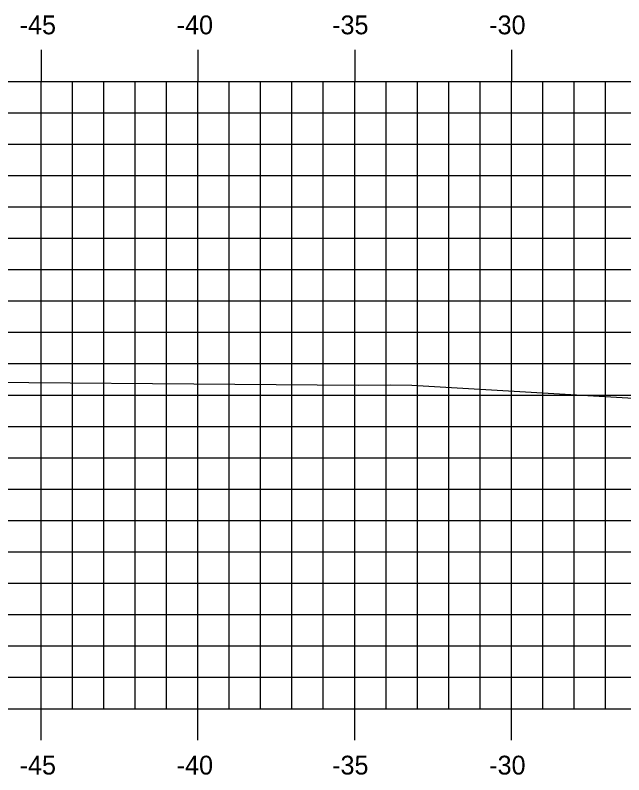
# Model space of a CAD drawing. Extents: x 1147855 to 1148025, y 608981 to 609091.
# Drawn here: x 1147892.39 to 1147911.79, y 609018.23 to 609042.44 of the extents above; entities that cross this region are included whole.
import ezdxf

# ---------------------------------------------------------------- set-up
doc = ezdxf.new("R2010")
doc.units = 0
for name, color, linetype in [('H_V ANNOTATION', 7, 'Continuous'), ('MAJOR', 7, 'Continuous'), ('MINOR', 7, 'Continuous'), ('S_Roadway_Centerline', 7, 'Continuous')]:
    doc.layers.add(name, color=color, linetype=linetype)

msp = doc.modelspace()

# ---------------------------------------------------------------- linework, layer by layer
at = {"layer": 'MAJOR'}
for p, q in [((1147893.211, 609041.337), (1147893.211, 609040.335)), ((1147898.211, 609041.337), (1147898.211, 609040.335)), ((1147903.211, 609041.337), (1147903.211, 609040.335)), ((1147908.211, 609041.337), (1147908.211, 609040.335)), ((1147868.211, 609040.335), (1148008.211, 609040.335)), ((1147868.211, 609040.335), (1148008.211, 609040.335)), ((1147893.211, 609020.335), (1147893.211, 609040.335)), ((1147898.211, 609020.335), (1147898.211, 609040.335)), ((1147903.211, 609020.335), (1147903.211, 609040.335)), ((1147908.211, 609020.335), (1147908.211, 609040.335)), ((1147868.211, 609035.335), (1148008.211, 609035.335)), ((1147868.211, 609030.335), (1148008.211, 609030.335)), ((1147868.211, 609025.335), (1148008.211, 609025.335)), ((1147868.211, 609020.335), (1148008.211, 609020.335)), ((1147868.211, 609020.335), (1148008.211, 609020.335)), ((1147893.211, 609019.333), (1147893.211, 609020.335)), ((1147898.211, 609019.333), (1147898.211, 609020.335)), ((1147903.211, 609019.333), (1147903.211, 609020.335)), ((1147908.211, 609019.333), (1147908.211, 609020.335))]:
    msp.add_line(p, q, dxfattribs=at)
at = {"layer": 'MINOR'}
for p, q in [((1147894.211, 609020.335), (1147894.211, 609040.335)), ((1147895.211, 609020.335), (1147895.211, 609040.335)), ((1147896.211, 609020.335), (1147896.211, 609040.335)), ((1147897.211, 609020.335), (1147897.211, 609040.335)), ((1147899.211, 609020.335), (1147899.211, 609040.335)), ((1147900.211, 609020.335), (1147900.211, 609040.335)), ((1147901.211, 609020.335), (1147901.211, 609040.335)), ((1147902.211, 609020.335), (1147902.211, 609040.335)), ((1147904.211, 609020.335), (1147904.211, 609040.335)), ((1147905.211, 609020.335), (1147905.211, 609040.335)), ((1147906.211, 609020.335), (1147906.211, 609040.335)), ((1147907.211, 609020.335), (1147907.211, 609040.335)), ((1147909.211, 609020.335), (1147909.211, 609040.335)), ((1147910.211, 609020.335), (1147910.211, 609040.335)), ((1147911.211, 609020.335), (1147911.211, 609040.335)), ((1147868.211, 609039.335), (1148008.211, 609039.335)), ((1147868.211, 609038.335), (1148008.211, 609038.335)), ((1147868.211, 609037.335), (1148008.211, 609037.335)), ((1147868.211, 609036.335), (1148008.211, 609036.335)), ((1147868.211, 609034.335), (1148008.211, 609034.335)), ((1147868.211, 609033.335), (1148008.211, 609033.335)), ((1147868.211, 609032.335), (1148008.211, 609032.335)), ((1147868.211, 609031.335), (1148008.211, 609031.335)), ((1147868.211, 609029.335), (1148008.211, 609029.335)), ((1147868.211, 609028.335), (1148008.211, 609028.335)), ((1147868.211, 609027.335), (1148008.211, 609027.335)), ((1147868.211, 609026.335), (1148008.211, 609026.335)), ((1147868.211, 609024.335), (1148008.211, 609024.335)), ((1147868.211, 609023.335), (1148008.211, 609023.335)), ((1147868.211, 609022.335), (1148008.211, 609022.335)), ((1147868.211, 609021.335), (1148008.211, 609021.335))]:
    msp.add_line(p, q, dxfattribs=at)
at = {"layer": 'S_Roadway_Centerline'}
msp.add_lwpolyline([(1147875.468, 609030.895), (1147878.817, 609030.82), (1147887.56, 609030.781), (1147903.328, 609030.651), (1147904.366, 609030.659), (1147905.033, 609030.646), (1147917.167, 609029.936)], dxfattribs=at)

# ---------------------------------------------------------------- texts
at = {"layer": 'H_V ANNOTATION'}
for s, p in [('-45', (1147892.528, 609041.835)), ('-40', (1147897.536, 609041.835)), ('-35', (1147902.491, 609041.835)), ('-30', (1147907.499, 609041.835)), ('-45', (1147892.528, 609018.235)), ('-40', (1147897.536, 609018.235)), ('-35', (1147902.491, 609018.235)), ('-30', (1147907.499, 609018.235))]:
    msp.add_text(s, height=0.6, dxfattribs=at).set_placement(p)

doc.saveas('drawing.dxf')
